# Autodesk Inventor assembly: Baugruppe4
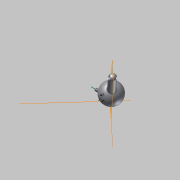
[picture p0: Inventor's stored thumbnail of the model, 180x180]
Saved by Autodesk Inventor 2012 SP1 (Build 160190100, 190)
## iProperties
Created: 2012-04
Part Number: Baugruppe4
Document SubType Name: Assembly
Designer: Standardbenutzer
Author: Standardbenutzer
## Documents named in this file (3)
- D:\Daten\Inventor\Baugruppe4.iam
- C:\Users\Standardbenutzer\Downloads\GlockeOseM8.ipt
- C:\Users\Standardbenutzer\Downloads\Kloppel-1.ipt
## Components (2 placed, 2 different names)
1. GlockeOseM8:1 — Passend:1, Tangential:1
2. Kloppel-1:1 — Passend:1, Tangential:1
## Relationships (2: Mate 1, Tangent 1)
- Passend:1 [Mate]: GlockeOseM8:1 ↔ Kloppel-1:1
- Tangential:1: GlockeOseM8:1 ↔ Kloppel-1:1
